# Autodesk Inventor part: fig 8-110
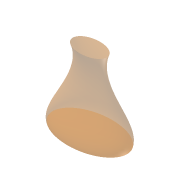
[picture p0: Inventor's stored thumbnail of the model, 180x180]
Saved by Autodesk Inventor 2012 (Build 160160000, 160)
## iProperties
Created: 2004-05
Part Number: fig 8-110
Document SubType Name: Modeling
Designer: CADCIM Technologies
Manufacturer: Standard
Standards Organization: Custom
Density: 1 g/cm^3
Material: Default
Author: CADCIM Technologies
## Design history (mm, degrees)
sketch "Sketch4"
  geometry: 1 further point; 1 other entity
  constraints: 2 other
workplane "Work Plane2"
sketch "Sketch5"
  geometry: 1 further point; 1 other entity
  constraints: 2 other
feature "LoftSrf1" sketch "Sketch5" dims "d4" = 20, "d5" = 110 deg, "d6" = 40, "d7" = 70 deg
patch "Boundary Patch1" dims "d8" = 0, "d9" = 0
patch "Boundary Patch2" dims "d10" = 0, "d11" = 0
patch "Boundary Patch3" dims "d12" = 0, "d13" = 0
body "Srf1"
body "Srf2"
body "Srf3"
body "Srf4"
other parameters: "d3" = 33.5
